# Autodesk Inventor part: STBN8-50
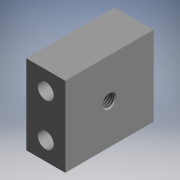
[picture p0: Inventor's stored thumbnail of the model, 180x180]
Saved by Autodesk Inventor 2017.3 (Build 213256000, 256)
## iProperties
Part Number: STBN8-50
Material: Generic
Catalog Web Link: www.cadenas.de
Description: STBN, STBS-Threaded Stopper Blocks - Counterbore
Vendor: MISUMI
Document SubType Name: Modeling
Designer: partserver
Manufacturer: MISUMI
Mass: 40.8111 g
Surface Area: 118.978 cm^2
Volume: 40.8111 cm^3
Density: 1 g/cm^3
Appearance: PSOLRGB-175-175-175
Category: PARTsolutions
Company: MISUMI
Title: STBN8-50
Author: Cadenas PARTsolutions
Comments: Threaded Stopper Blocks - Counterbore
PSOL_IDENT_0: {$CADENAS_DATA\23d-libs\misumi\metric\15_locating_components\stbn.prj},168 {VTYP=3D},{NB=STBN8-50},{
PSOL_IDENT_1: LINA=STBN8-50},{NN=STBN, STBS},{DATE=02.06.2021 05:59:34},{GEOMDATE=26.10.2015 04:34:12},{VERSION=},
PSOL_IDENT_2: {LINEID=50},{WBVAR=TRS,HS},{WBNUMERIC=HS}  {NB=STBN8-50},{LINA=STBN8-50},{KT=DUMMY},{PN=STBN8-50},{T
PSOL_IDENT_3: RS=CT},{TYPE=STBN},{MAT=Low Carbon Steel},{ST=Zinc Galvanizing},{M=8},{HS=50},{H1=30,'30',50,'50'},{
PSOL_IDENT_4: MP=8x1.25},{MC=8x1.25},{MCMIN=6.647},{MF=8x0.75},{MFMIN=7.188},{MMAJ=8},{MMIN=6.647},{L=45},{P=24}
NB: STBN8-50
NN: STBN, STBS
NT: Threaded Stopper Blocks - Counterbore
NBSYN: $PN.
LINA: STBN8-50
CATALOG: Misumi
PN: STBN8-50
TRS: Coarse Thread
MAT: Low Carbon Steel
ST: Zinc Galvanizing
M: 8
HS: 50
MP: 8x1.25
L: 45
P: 24
SUPPLIER: MISUMI
ARTICLENO: STBN8-50
BOMINFO: STBN8-50
CREATOR: CADENAS GmbH
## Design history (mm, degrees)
sketch "Sketch_1"
  geometry: L1 (50, 22.5)-(0, 22.5); L2 (0, 22.5)-(0, -22.5); L3 (0, -22.5)-(50, -22.5); L4 (50, -22.5)-(50, 22.5)
  constraints: 8 end point
extrude "Extrusion1" join sketch "Sketch_1" stored distance "d0" = 22; taper "d1" = 0 deg
sketch "Sketch2"
  geometry: 1 further point
hole "Hole1" sketch "Sketch2" at (11, 34.5) diameter "d2" = 9; stored, may be unused: countersink angle "d6" = 90 deg, drill point angle "d8" = 0 deg; dims "d3" = 6, "d4" = 14, "d5" = 8.6, "d7" = 50
sketch "Sketch3"
  geometry: 1 further point
hole "Hole2" sketch "Sketch3" at (11, 10.5) diameter "d9" = 9; stored, may be unused: countersink angle "d13" = 90 deg, drill point angle "d15" = 0 deg; dims "d10" = 6, "d11" = 14, "d12" = 8.6, "d14" = 50
sketch "Sketch_4"
  geometry: L1 (11, 25)-(-11, 25); L2 (-11, 25)-(-11, 29); L3 (-11, 29)-(-10.323, 28.323); L4 (-10.323, 28.323)-(10.323, 28.323); L5 (10.323, 28.323)-(11, 29); L6 (11, 29)-(11, 25); L7 (11, 25)-(-11, 25)
  constraints: 14 end point
revolve "Revolution1" sketch "Sketch_4" stored, may be unused: angle "d16" = 360 deg
thread "Thread1" dims "d17" = 20.647, "d18" = 0
node "blosk_to_screw_XY"
node "blosk_to_screw_YZ"
node "blosk_to_screw_ZX"
node "blosk_to_screw_X"
node "blosk_to_screw_Y"
node "blosk_to_screw_Z"
node "blosk_to_screw_Center"
body "Solid1"
